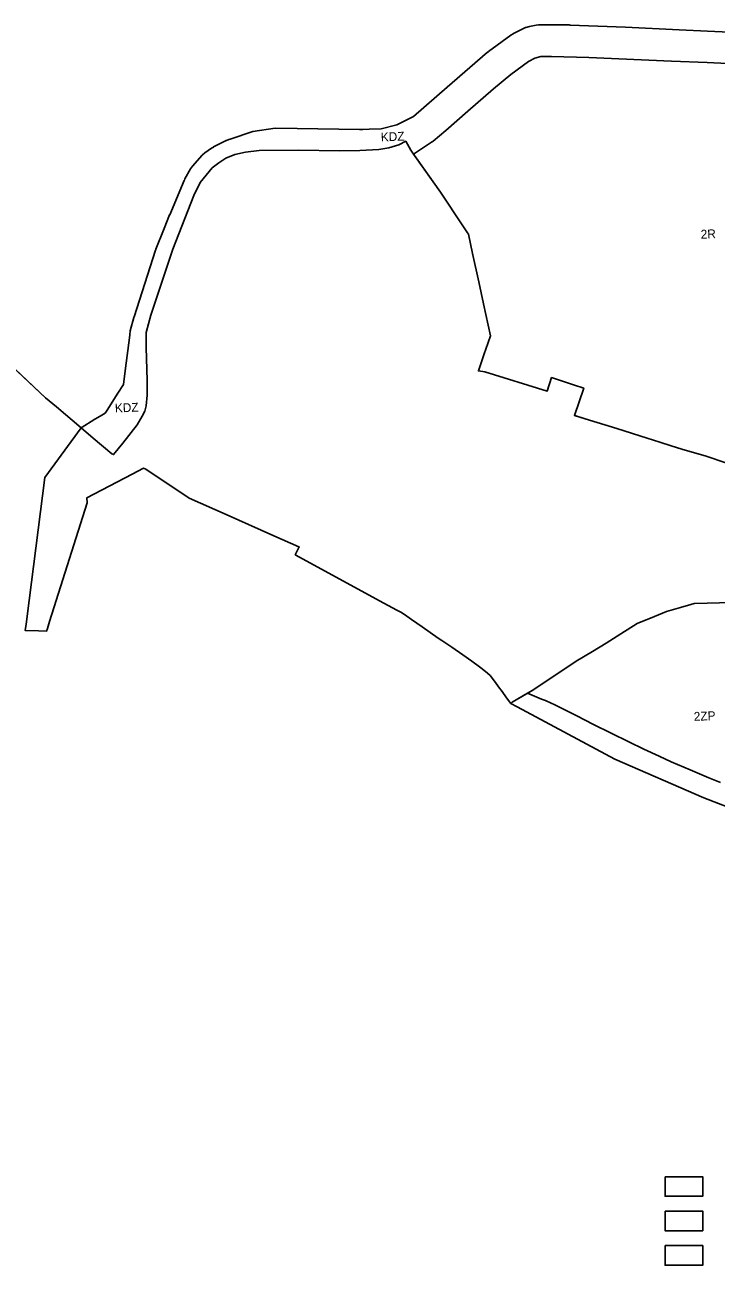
# Model space of a CAD drawing. Extents: x 7417062 to 7419348, y 5549957 to 5551711.
# Drawn here: x 7417827 to 7418374, y 5550011 to 5550992 of the extents above; entities that cross this region are included whole.
import ezdxf

# ---------------------------------------------------------------- set-up
doc = ezdxf.new("R2010")
doc.units = 0
for name, color, linetype in [('GRANICA_PLANU_po_wejsciu_MYDLNIKI', 7, 'Continuous'), ('linie_rozgraniczające_po_wejsciu_MYDLNIKI', 7, 'Continuous'), ('oznaczenia_przeznaczen_po_wejsciu_MYDLNIKI', 7, 'Continuous'), ('Tereny dla których obowiązuje MPZP Bronowice_Male_tetmajera_', 7, 'Continuous'), ('Tereny dla których obowiązuje MPZP Lindego', 7, 'Continuous'), ('Tereny dla których obowiązuje MPZP Mydlniki', 7, 'Continuous')]:
    doc.layers.add(name, color=color, linetype=linetype)

msp = doc.modelspace()

# ---------------------------------------------------------------- linework, layer by layer
at = {"layer": 'GRANICA_PLANU_po_wejsciu_MYDLNIKI'}
msp.add_line((7418211.61, 5550455.11), (7418212.67, 5550456.1), dxfattribs=at)
for points in [[(7418381.48, 5550645.57), (7418366.08, 5550650.65), (7418346.77, 5550656.35), (7418338.42, 5550658.94), (7418329.44, 5550661.72), (7418319.26, 5550664.87), (7418295.31, 5550672.54), (7418270.42, 5550680.35), (7418262.14, 5550682.95), (7418261.88, 5550683.03), (7418269.14, 5550704.53), (7418261.23, 5550707.12), (7418252.4, 5550710.11), (7418243.71, 5550712.91), (7418240.31, 5550702.29), (7418190.89, 5550717.39), (7418185.88, 5550718.24), (7418190.58, 5550731.6), (7418191.91, 5550735.48), (7418195.47, 5550745.84), (7418189.97, 5550771.19), (7418186.18, 5550788.63), (7418181.29, 5550811.16), (7418178.01, 5550826.26), (7418177.18, 5550827.51), (7418173.54, 5550832.99), (7418155.92, 5550859.51), (7418133.59, 5550891.2), (7418132.4, 5550892.89), (7418128.44, 5550899.83), (7418122.9, 5550896.9), (7418114.99, 5550894.55), (7418107.25, 5550893.28), (7418092.04, 5550892.67), (7418076.48, 5550892.36), (7418043.54, 5550892.72), (7418012.49, 5550892.66), (7418001.86, 5550891.33), (7417993.39, 5550889.27), (7417986.33, 5550886.37), (7417980.57, 5550882.81), (7417975.5, 5550878.9), (7417966.04, 5550867.27), (7417961.05, 5550856.89), (7417944.32, 5550814.46), (7417926.92, 5550762.35), (7417923.29, 5550748.57), (7417923.21, 5550736.79), (7417923.96, 5550710.7), (7417923.96, 5550698.93), (7417923.29, 5550690.46), (7417922.15, 5550686.34), (7417920.09, 5550682.27), (7417916.14, 5550675.54), (7417904.79, 5550661.06), (7417897.42, 5550651.95), (7417896.21, 5550652.5), (7417881.4, 5550665.03), (7417871.75, 5550673.2)], [(7417871.75, 5550673.2), (7417852.22, 5550689.73), (7417843.71, 5550696.94), (7417798.86, 5550738.94)], [(7418212.67, 5550456.1), (7418229.01, 5550465.67), (7418241.08, 5550473.75), (7418253.33, 5550481.97), (7418263.3, 5550488.48), (7418276.11, 5550496.1), (7418287.05, 5550502.8), (7418298.47, 5550510.1), (7418311.32, 5550518.33), (7418325.09, 5550523.95), (7418334.66, 5550527.85), (7418345.69, 5550531.09), (7418353.85, 5550533.49), (7418356.61, 5550534.3), (7418366.66, 5550534.5), (7418376.46, 5550534.68)], [(7418913.17, 5550230.8), (7418797.38, 5550252.01), (7418769.21, 5550258.51), (7418725.47, 5550267.96), (7418652.56, 5550283.78), (7418587.07, 5550302.96), (7418460.75, 5550342.97), (7418425.56, 5550356.68), (7418364.15, 5550380.58), (7418293.85, 5550411.16), (7418216.45, 5550452.52), (7418211.61, 5550455.11)]]:
    msp.add_lwpolyline(points, dxfattribs=at)
at = {"layer": 'linie_rozgraniczające_po_wejsciu_MYDLNIKI'}
for p, q in [((7418211.6, 5550983.87), (7418194, 5550970.89)), ((7418213.46, 5550984.97), (7418211.6, 5550983.87)), ((7418213.6, 5550985.07), (7418213.46, 5550984.97)), ((7418223.28, 5550989.73), (7418213.6, 5550985.07)), ((7418223.37, 5550989.75), (7418223.28, 5550989.73)), ((7418223.45, 5550989.81), (7418223.37, 5550989.75)), ((7418226.35, 5550990.74), (7418223.45, 5550989.81)), ((7418231.64, 5550991.76), (7418226.35, 5550990.74)), ((7418233.48, 5550991.97), (7418231.64, 5550991.76)), ((7418233.79, 5550991.92), (7418233.48, 5550991.97)), ((7418234.06, 5550991.98), (7418233.79, 5550991.92)), ((7418256.68, 5550991.86), (7418234.06, 5550991.98)), ((7418257.26, 5550991.86), (7418256.68, 5550991.86)), ((7418257.32, 5550991.85), (7418257.26, 5550991.86)), ((7418257.52, 5550991.85), (7418257.32, 5550991.85)), ((7418257.71, 5550991.85), (7418257.52, 5550991.85)), ((7418258.41, 5550991.79), (7418257.71, 5550991.85)), ((7418302.33, 5550990.01), (7418258.41, 5550991.79)), ((7418344.66, 5550988.09), (7418302.33, 5550990.01)), ((7418367.16, 5550987.05), (7418344.66, 5550988.09)), ((7418401.67, 5550985.46), (7418367.16, 5550987.05)), ((7418193.23, 5550970.27), (7418161.3, 5550942.59)), ((7418193.52, 5550970.46), (7418193.23, 5550970.27)), ((7418194, 5550970.89), (7418193.52, 5550970.46)), ((7418225.5, 5550963.05), (7418230.62, 5550965.52)), ((7418230.62, 5550965.52), (7418235.15, 5550966.98)), ((7418235.15, 5550966.98), (7418243.82, 5550966.93)), ((7418243.82, 5550966.93), (7418273.14, 5550966.19)), ((7418273.14, 5550966.19), (7418338.65, 5550963.34)), ((7418338.65, 5550963.34), (7418366.87, 5550962.04)), ((7418211.45, 5550952.7), (7418225.5, 5550963.05)), ((7418366.87, 5550962.04), (7418382.91, 5550961.3)), ((7418197.88, 5550941.22), (7418211.45, 5550952.7)), ((7418161.3, 5550942.59), (7418134.5, 5550919.5)), ((7418177.66, 5550923.69), (7418197.88, 5550941.22)), ((7418133.96, 5550919.14), (7418121.44, 5550912.79)), ((7418134.5, 5550919.5), (7418133.96, 5550919.14)), ((7418160.04, 5550908.5), (7418177.66, 5550923.69)), ((7418007.63, 5550907.55), (7417989.66, 5550901.45)), ((7418025.25, 5550910.2), (7418007.63, 5550907.55)), ((7418042.71, 5550909.86), (7418025.25, 5550910.2)), ((7418091.91, 5550909.18), (7418042.71, 5550909.86)), ((7418094.57, 5550909.28), (7418091.91, 5550909.18)), ((7418099.59, 5550909.46), (7418094.57, 5550909.28)), ((7418109.01, 5550909.81), (7418099.59, 5550909.46)), ((7418121.44, 5550912.79), (7418109.01, 5550909.81)), ((7418150.19, 5550900.02), (7418160.04, 5550908.5)), ((7417974.89, 5550894.39), (7417969.71, 5550890.71)), ((7417976.38, 5550895.25), (7417974.89, 5550894.39)), ((7417976.56, 5550895.39), (7417976.38, 5550895.25)), ((7417986.49, 5550900.33), (7417976.56, 5550895.39)), ((7417986.66, 5550900.37), (7417986.49, 5550900.33)), ((7417986.81, 5550900.48), (7417986.66, 5550900.37)), ((7417988.62, 5550901.15), (7417986.81, 5550900.48)), ((7417989.66, 5550901.45), (7417988.62, 5550901.15)), ((7418134.72, 5550889.6), (7418145.66, 5550896.93)), ((7418145.66, 5550896.93), (7418148.86, 5550899.02)), ((7418148.86, 5550899.02), (7418149.39, 5550899.38)), ((7418149.39, 5550899.38), (7418150.04, 5550899.88)), ((7418150.04, 5550899.88), (7418150.19, 5550900.02)), ((7417967.61, 5550888.84), (7417959.96, 5550880.26)), ((7417967.69, 5550888.9), (7417967.61, 5550888.84)), ((7417967.75, 5550888.99), (7417967.69, 5550888.9)), ((7417969.71, 5550890.71), (7417967.75, 5550888.99)), ((7417958.41, 5550878.1), (7417953.93, 5550870.18)), ((7417959.83, 5550880.05), (7417958.41, 5550878.1)), ((7417959.96, 5550880.26), (7417959.83, 5550880.05)), ((7417953.29, 5550868.88), (7417941.86, 5550841.75)), ((7417953.42, 5550869.09), (7417953.29, 5550868.88)), ((7417953.93, 5550870.18), (7417953.42, 5550869.09)), ((7417941.77, 5550841.53), (7417937.5, 5550830.84)), ((7417941.84, 5550841.64), (7417941.77, 5550841.53)), ((7417941.86, 5550841.75), (7417941.84, 5550841.64)), ((7417937.5, 5550830.84), (7417930.99, 5550814.56)), ((7417930.71, 5550813.78), (7417913.65, 5550761.08)), ((7417930.92, 5550814.14), (7417930.71, 5550813.78)), ((7417930.99, 5550814.56), (7417930.92, 5550814.14)), ((7417913.45, 5550760.42), (7417910.68, 5550749.91)), ((7417913.64, 5550761), (7417913.45, 5550760.42)), ((7417913.65, 5550761.08), (7417913.64, 5550761)), ((7417910.68, 5550749.91), (7417910.33, 5550746.68)), ((7417843.71, 5550696.94), (7417798.86, 5550738.94)), ((7417910.27, 5550746.34), (7417906.76, 5550718.37)), ((7417910.33, 5550746.68), (7417910.27, 5550746.34)), ((7417906.76, 5550718.37), (7417905.39, 5550707.43)), ((7417900.96, 5550700.58), (7417892.27, 5550687.14)), ((7417905.39, 5550707.43), (7417900.96, 5550700.58)), ((7418269.14, 5550704.53), (7418261.88, 5550683.03)), ((7418269.14, 5550704.53), (7418269.14, 5550704.53)), ((7417886.95, 5550682.48), (7417882.73, 5550679.91)), ((7417890.75, 5550684.79), (7417886.95, 5550682.48)), ((7417892.27, 5550687.14), (7417890.75, 5550684.79)), ((7418345.69, 5550531.09), (7418334.66, 5550527.85)), ((7418229.01, 5550465.67), (7418224.8, 5550463.2)), ((7418235.86, 5550458.62), (7418224.8, 5550463.2)), ((7418238.87, 5550457.37), (7418235.86, 5550458.62)), ((7418238.88, 5550457.36), (7418238.87, 5550457.37)), ((7418238.89, 5550457.36), (7418238.88, 5550457.36)), ((7418243.48, 5550455.42), (7418238.89, 5550457.36)), ((7418245.76, 5550454.27), (7418243.48, 5550455.42)), ((7418263.62, 5550445.26), (7418245.76, 5550454.27)), ((7418277.02, 5550438.5), (7418263.62, 5550445.26)), ((7418304.74, 5550424.69), (7418277.02, 5550438.5)), ((7418316.69, 5550418.86), (7418304.74, 5550424.69)), ((7418328.74, 5550413.33), (7418316.69, 5550418.86)), ((7418338.29, 5550408.98), (7418328.74, 5550413.33)), ((7418353.27, 5550402.51), (7418338.29, 5550408.98)), ((7418368.17, 5550396.22), (7418353.27, 5550402.51)), ((7418377.35, 5550392.48), (7418368.17, 5550396.22))]:
    msp.add_line(p, q, dxfattribs=at)
for points in [[(7417871.75, 5550673.2), (7417881.4, 5550665.03), (7417896.21, 5550652.5), (7417897.42, 5550651.95), (7417904.79, 5550661.06), (7417916.14, 5550675.54), (7417920.09, 5550682.27), (7417922.15, 5550686.34), (7417923.29, 5550690.46), (7417923.96, 5550698.93), (7417923.96, 5550710.7), (7417923.21, 5550736.79), (7417923.29, 5550748.57), (7417926.92, 5550762.35), (7417944.32, 5550814.46), (7417961.05, 5550856.89), (7417966.04, 5550867.27), (7417975.5, 5550878.9), (7417980.57, 5550882.81), (7417986.33, 5550886.37), (7417993.39, 5550889.27), (7418001.86, 5550891.33), (7418012.49, 5550892.66), (7418043.54, 5550892.72), (7418076.48, 5550892.36), (7418092.04, 5550892.67), (7418107.25, 5550893.28), (7418114.99, 5550894.55), (7418122.9, 5550896.9), (7418128.44, 5550899.83), (7418132.4, 5550892.89), (7418133.59, 5550891.2), (7418134.72, 5550889.6)], [(7418185.88, 5550718.24), (7418190.58, 5550731.6), (7418191.91, 5550735.48), (7418195.47, 5550745.84), (7418189.97, 5550771.19), (7418186.18, 5550788.63), (7418181.29, 5550811.16), (7418178.01, 5550826.26), (7418177.18, 5550827.51), (7418173.54, 5550832.99), (7418155.92, 5550859.51), (7418134.72, 5550889.6)], [(7418185.88, 5550718.24), (7418190.89, 5550717.39), (7418240.31, 5550702.29), (7418243.71, 5550712.91), (7418252.4, 5550710.11), (7418261.23, 5550707.12), (7418269.14, 5550704.53)], [(7417871.73, 5550673.22), (7417852.22, 5550689.73), (7417843.71, 5550696.94)], [(7417882.73, 5550679.91), (7417871.73, 5550673.22), (7417871.75, 5550673.2)], [(7418261.88, 5550683.03), (7418270.42, 5550680.35), (7418295.31, 5550672.54)], [(7418295.31, 5550672.54), (7418319.26, 5550664.87), (7418329.44, 5550661.72), (7418338.42, 5550658.94)], [(7418338.42, 5550658.94), (7418346.77, 5550656.35), (7418366.08, 5550650.65)], [(7418366.08, 5550650.65), (7418381.48, 5550645.57), (7418390.06, 5550642.57), (7418400, 5550639.09), (7418391.35, 5550612.87), (7418390.19, 5550609.18), (7418400.01, 5550606.16), (7418391.97, 5550581.75), (7418400.59, 5550579.06), (7418408.99, 5550576.44)], [(7418345.69, 5550531.09), (7418353.85, 5550533.49), (7418356.61, 5550534.3)], [(7418356.61, 5550534.3), (7418366.66, 5550534.5), (7418376.46, 5550534.68), (7418386.25, 5550534.87)], [(7418334.66, 5550527.85), (7418325.09, 5550523.95), (7418311.32, 5550518.33)], [(7418311.32, 5550518.33), (7418298.47, 5550510.1), (7418287.05, 5550502.8), (7418276.11, 5550496.1), (7418263.3, 5550488.48)], [(7418263.3, 5550488.48), (7418253.33, 5550481.97), (7418241.08, 5550473.75), (7418229.01, 5550465.67)], [(7418211.61, 5550455.11), (7418212.67, 5550456.1), (7418224.8, 5550463.2)], [(7418913.17, 5550230.8), (7418797.38, 5550252.01), (7418769.21, 5550258.51), (7418725.47, 5550267.96), (7418652.56, 5550283.78), (7418587.07, 5550302.96), (7418460.75, 5550342.97), (7418425.56, 5550356.68), (7418364.15, 5550380.58), (7418293.85, 5550411.16), (7418216.45, 5550452.52), (7418211.61, 5550455.11)]]:
    msp.add_lwpolyline(points, dxfattribs=at)
at = {"layer": 'Tereny dla których obowiązuje MPZP Bronowice_Male_tetmajera_'}
msp.add_lwpolyline([(7418333.49, 5550080.75), (7418363.29, 5550080.75), (7418363.29, 5550065.28), (7418333.49, 5550065.28)], close=True, dxfattribs=at)
msp.add_lwpolyline([(7418333.49, 5550080.75), (7418363.29, 5550080.75), (7418363.29, 5550065.28), (7418333.49, 5550065.28)], close=True, dxfattribs=at)
at = {"layer": 'Tereny dla których obowiązuje MPZP Lindego'}
for points in [[(7418333.49, 5550053.48), (7418363.29, 5550053.48), (7418363.29, 5550038.01), (7418333.49, 5550038.01)], [(7418333.49, 5550053.48), (7418363.29, 5550053.48), (7418363.29, 5550038.01), (7418333.49, 5550038.01)], [(7418333.49, 5550026.21), (7418363.29, 5550026.21), (7418363.29, 5550010.74), (7418333.49, 5550010.74)]]:
    msp.add_lwpolyline(points, close=True, dxfattribs=at)
at = {"layer": 'Tereny dla których obowiązuje MPZP Mydlniki'}
msp.add_line((7417871.75, 5550673.2), (7417843.14, 5550633.85), dxfattribs=at)
for points in [[(7418381.48, 5550645.57), (7418366.08, 5550650.65), (7418346.77, 5550656.35), (7418338.42, 5550658.94), (7418329.44, 5550661.72), (7418319.26, 5550664.87), (7418295.31, 5550672.54), (7418270.42, 5550680.35), (7418262.14, 5550682.95), (7418261.88, 5550683.03), (7418269.14, 5550704.53), (7418261.23, 5550707.12), (7418252.4, 5550710.11), (7418243.71, 5550712.91), (7418240.31, 5550702.29), (7418190.89, 5550717.39), (7418185.88, 5550718.24), (7418190.58, 5550731.6), (7418191.91, 5550735.48), (7418195.47, 5550745.84), (7418189.97, 5550771.19), (7418186.18, 5550788.63), (7418181.29, 5550811.16), (7418178.01, 5550826.26), (7418177.18, 5550827.51), (7418173.54, 5550832.99), (7418155.92, 5550859.51), (7418133.59, 5550891.2), (7418132.4, 5550892.89), (7418128.44, 5550899.83), (7418122.9, 5550896.9), (7418114.99, 5550894.55), (7418107.25, 5550893.28), (7418092.04, 5550892.67), (7418076.48, 5550892.36), (7418043.54, 5550892.72), (7418012.49, 5550892.66), (7418001.86, 5550891.33), (7417993.39, 5550889.27), (7417986.33, 5550886.37), (7417980.57, 5550882.81), (7417975.5, 5550878.9), (7417966.04, 5550867.27), (7417961.05, 5550856.89), (7417944.32, 5550814.46), (7417926.92, 5550762.35), (7417923.29, 5550748.57), (7417923.21, 5550736.79), (7417923.96, 5550710.7), (7417923.96, 5550698.93), (7417923.29, 5550690.46), (7417922.15, 5550686.34), (7417920.09, 5550682.27), (7417916.14, 5550675.54), (7417904.79, 5550661.06), (7417897.42, 5550651.95), (7417896.21, 5550652.5), (7417881.4, 5550665.03), (7417871.75, 5550673.2)], [(7417843.14, 5550633.85), (7417830.69, 5550536.48), (7417828.29, 5550517.73), (7417827.65, 5550512.75), (7417838.2, 5550512.52), (7417844.45, 5550512.39), (7417845.27, 5550514.42), (7417846.81, 5550520.04), (7417876.47, 5550613.94), (7417876.38, 5550617.91), (7417912.1, 5550636.57), (7417921.12, 5550641.28), (7417922.94, 5550640.46), (7417957.32, 5550617.55), (7417986.52, 5550604.59), (7418024.24, 5550587.84), (7418044.06, 5550579.04), (7418044.23, 5550578.96), (7418041.11, 5550572.74), (7418111.27, 5550534.46), (7418121.33, 5550528.97), (7418125.07, 5550526.95), (7418129.21, 5550524.07), (7418133.01, 5550521.42), (7418141.37, 5550515.74), (7418154.22, 5550506.89), (7418156.9, 5550505.05), (7418164.85, 5550499.58), (7418173.62, 5550493.54), (7418180.79, 5550488.6), (7418186.82, 5550484.02), (7418188.88, 5550482.45), (7418193.02, 5550479.12), (7418195.3, 5550477.11), (7418199.43, 5550471.68), (7418201.87, 5550468.27), (7418204.62, 5550464.58), (7418208.22, 5550459.67), (7418211.61, 5550455.11)], [(7418211.61, 5550455.11), (7418212.67, 5550456.1), (7418229.01, 5550465.67), (7418241.08, 5550473.75), (7418253.33, 5550481.97), (7418263.3, 5550488.48), (7418276.11, 5550496.1), (7418287.05, 5550502.8), (7418298.47, 5550510.1), (7418311.32, 5550518.33), (7418325.09, 5550523.95), (7418334.66, 5550527.85), (7418345.69, 5550531.09), (7418353.85, 5550533.49), (7418356.61, 5550534.3), (7418366.66, 5550534.5), (7418376.46, 5550534.68)]]:
    msp.add_lwpolyline(points, dxfattribs=at)
msp.add_lwpolyline([(7418333.49, 5550026.21), (7418363.29, 5550026.21), (7418363.29, 5550010.74), (7418333.49, 5550010.74)], close=True, dxfattribs=at)

# ---------------------------------------------------------------- texts
at = {"layer": 'oznaczenia_przeznaczen_po_wejsciu_MYDLNIKI'}
for s, p in [('KDZ', (7418108.89, 5550899.66)), ('2R', (7418361.81, 5550822.75)), ('KDZ', (7417898.63, 5550685.25)), ('2ZP', (7418356.34, 5550441.32))]:
    msp.add_text(s, height=7, rotation=2.32296, dxfattribs=at).set_placement(p)

doc.saveas('drawing.dxf')
